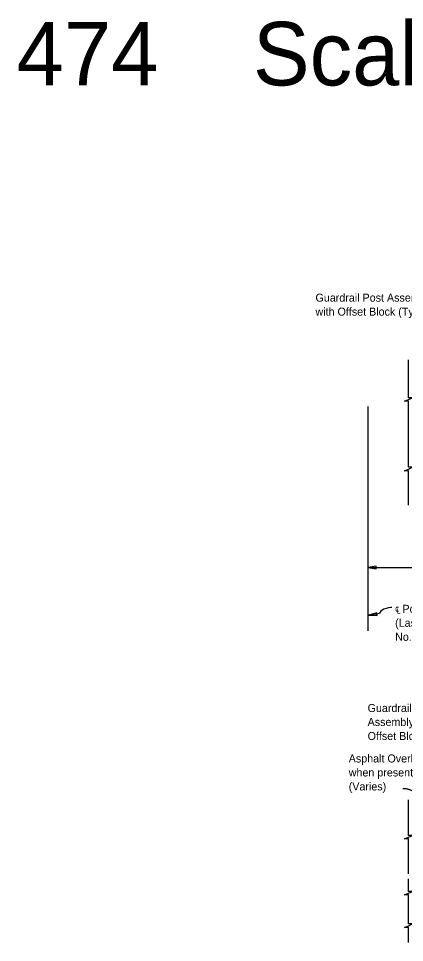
# Model space of a CAD drawing. Extents: x 21665 to 21741.5, y 56121.9 to 56164.2.
# Drawn here: x 21665.03 to 21674.74, y 56140.9 to 56164.17 of the extents above; entities that cross this region are included whole.
import ezdxf

# ---------------------------------------------------------------- set-up
doc = ezdxf.new("R2010")
doc.units = 0
doc.layers.add('Dimension', color=7, linetype='Continuous')
doc.layers.add('TextStructures', color=7, linetype='Continuous')

msp = doc.modelspace()

# ---------------------------------------------------------------- linework, layer by layer
at = {"layer": 'Dimension'}
msp.add_line((21673.826, 56148.751), (21673.826, 56154.396), dxfattribs=at)
for points in [[(21674.845, 56153.53), (21674.845, 56154.528), (21674.742, 56154.528), (21674.845, 56154.573), (21674.948, 56154.618), (21674.845, 56154.618), (21674.845, 56155.571)], [(21674.845, 56151.911), (21674.845, 56152.778), (21674.742, 56152.778), (21674.845, 56152.823), (21674.948, 56152.868), (21674.845, 56152.868), (21674.845, 56153.53)], [(21673.826, 56150.343), (21679.43, 56150.343), (21679.43, 56150.447), (21679.475, 56150.343), (21679.52, 56150.24), (21679.52, 56150.343), (21693.43, 56150.343)], [(21674.845, 56142.634), (21674.845, 56143.509), (21674.742, 56143.509), (21674.845, 56143.554), (21674.948, 56143.599), (21674.845, 56143.599), (21674.845, 56144.498)], [(21674.845, 56141.669), (21674.845, 56142.099), (21674.742, 56142.099), (21674.845, 56142.144), (21674.948, 56142.189), (21674.845, 56142.189), (21674.845, 56142.504)], [(21674.845, 56140.902), (21674.845, 56141.279), (21674.742, 56141.279), (21674.845, 56141.324), (21674.948, 56141.369), (21674.845, 56141.369), (21674.845, 56141.669)]]:
    msp.add_lwpolyline(points, dxfattribs=at)
for points in [[(21673.826, 56150.343), (21674.034, 56150.308), (21674.034, 56150.378)], [(21673.843, 56149.14), (21674.054, 56149.134), (21674.044, 56149.204)]]:
    msp.add_lwpolyline(points, close=True, dxfattribs=at)
for points, degree in [([(21674.427, 56149.336), (21674.406, 56149.334), (21674.183, 56149.318), (21674.11, 56149.172), (21674.077, 56149.173), (21673.843, 56149.14)], 3), ([(21675.349, 56141.887), (21675.447, 56144.15), (21674.983, 56144.782), (21674.706, 56144.775)], 2)]:
    msp.add_open_spline(points, degree=degree, dxfattribs=at)

# ---------------------------------------------------------------- texts
for s, p in [('Guardrail Post Assembly', (21672.505, 56157.036)), ('with Offset Block (Typ.)', (21672.505, 56156.684)), ('℄ Post Bolts', (21674.508, 56149.202)), ('(Last Index', (21674.508, 56148.85)), ('No. 474 Post)', (21674.508, 56148.498)), ('Guardrail Post', (21673.816, 56146.705)), ('Assembly with', (21673.816, 56146.353)), ('Offset Block (Typ.)', (21673.816, 56146.001)), ('Asphalt Overlay', (21673.341, 56145.435)), ('when present', (21673.341, 56145.083)), ('(Varies)', (21673.341, 56144.731))]:
    msp.add_text(s, height=0.2016, dxfattribs=at).set_placement(p)
at = {"layer": 'TextStructures'}
msp.add_text('474    Scale ', height=1.6, dxfattribs=at).set_placement((21664.983, 56162.48))

doc.saveas('drawing.dxf')
